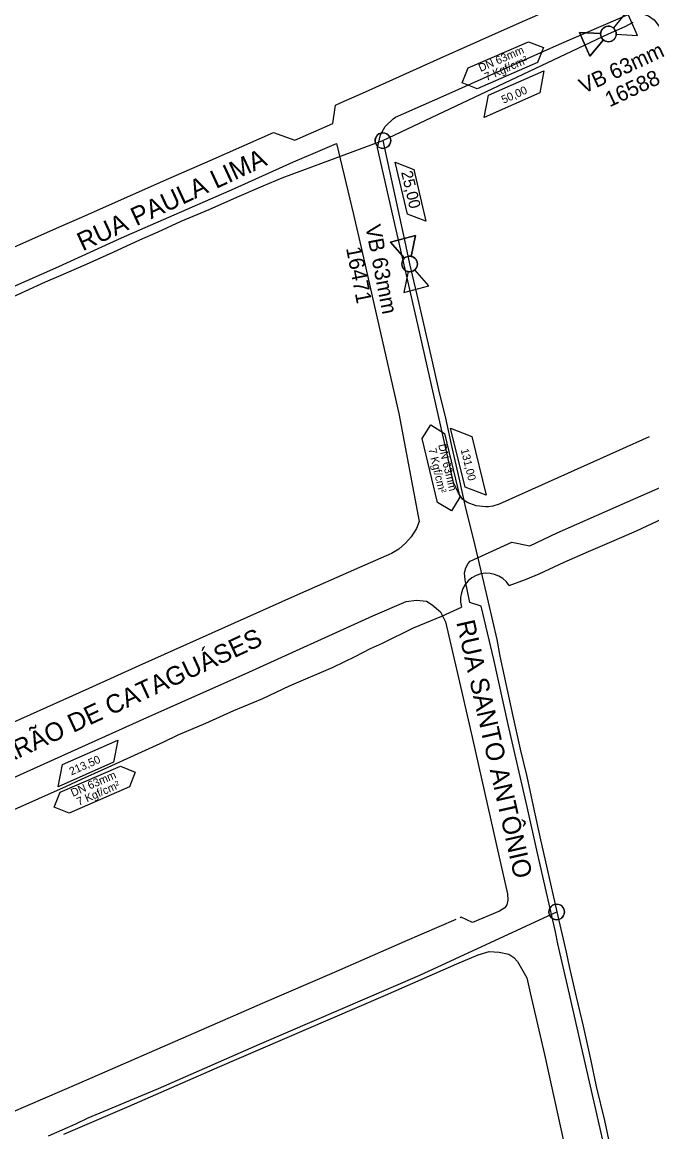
# Model space of a CAD drawing. Extents: x 656692 to 673945, y 7585994 to 7599066.
# Drawn here: x 669344.7 to 669589.7, y 7595459.1 to 7595890.6 of the extents above; entities that cross this region are included whole.
import ezdxf

# ---------------------------------------------------------------- set-up
doc = ezdxf.new("R2010")
doc.units = 0
for name, color, linetype in [('LOGRADOURO', 7, 'Continuous'), ('LOGRADOURO_TEXTO', 7, 'Continuous'), ('SIMBOLO', 7, 'Continuous'), ('TEXTO', 7, 'Continuous'), ('TUBO_PEAD_GN_63', 7, 'Continuous'), ('VALVULA_PEAD_63', 7, 'Continuous')]:
    doc.layers.add(name, color=color, linetype=linetype)

# ---------------------------------------------------------------- blocks, each defined once
blk = doc.blocks.new('VALVULA_PEAD_DN_16')
at = {"layer": 'VALVULA_PEAD_63'}
for points in [[(-0.0374, 0.0187), (-0.1395, 0.0698), (-0.1395, -0.0698), (-0.0374, -0.0187)], [(-0.0374, -0.0187), (-0.1395, -0.0698), (-0.1395, 0.0698), (-0.0374, 0.0187)], [(0.0374, -0.0187), (0.1395, -0.0698), (0.1395, 0.0698), (0.0374, 0.0187)], [(0.0374, -0.0187), (0.1395, -0.0698), (0.1395, 0.0698), (0.0374, 0.0187)]]:
    blk.add_lwpolyline(points, dxfattribs=at)
blk.add_circle((0, 0), 0.0419, dxfattribs=at)
for start, end in [(90, 270), (153.43495, 206.56505), (270, 90), (333.43495, 26.56505)]:
    blk.add_arc((0, 0), 0.0419, start, end, dxfattribs=at)
blk = doc.blocks.new('INTERLIGACAO_9')
at = {"layer": 'SIMBOLO'}
blk.add_circle((0, 0), 4.19, dxfattribs=at)
for start, end in [(0, 180), (180, 0)]:
    blk.add_arc((0, 0), 4.19, start, end, dxfattribs=at)

msp = doc.modelspace()

# ---------------------------------------------------------------- linework, layer by layer
at = {"layer": 'LOGRADOURO'}
for points in [[(669321.54, 7595794.23), (669359.27, 7595810.97), (669367.95, 7595814.75), (669399.74, 7595828.85), (669417.79, 7595836.75), (669442.46, 7595847.64), (669450.75, 7595844.67), (669458.2, 7595847.94), (669465.54, 7595851.19), (669466.64, 7595858.35), (669468.76, 7595859.3), (669477.05, 7595862.95), (669507.28, 7595876.53), (669538.25, 7595890.25), (669575.02, 7595906.45), (669577.47, 7595909.7), (669578.46, 7595912.59), (669578.58, 7595916.4)], [(669553.79, 7595882.06), (669580.42, 7595893.61), (669582.82, 7595894.1), (669585.35, 7595894.02), (669588.34, 7595892.98), (669590.53, 7595891.47), (669592.25, 7595889.23), (669594.49, 7595885.22), (669611.97, 7595846.58), (669622.46, 7595823.54), (669633.74, 7595799.1), (669648.11, 7595768.42), (669649.11, 7595765.62), (669649.81, 7595762.99), (669649.9, 7595759.85), (669649.5, 7595757.16), (669648.42, 7595754.65), (669646.35, 7595751.78), (669644.89, 7595750.78), (669637.86, 7595747.18), (669632.34, 7595749.1), (669607.54, 7595737.68)], [(669588.64, 7595729.3), (669577.06, 7595724.09), (669553.14, 7595713.41), (669530.33, 7595703.1), (669527.84, 7595702.32), (669526.19, 7595702.1), (669525.04, 7595702.06), (669521.31, 7595702.51), (669517.78, 7595703.74), (669515.95, 7595705.11), (669514.4, 7595707.37), (669512.57, 7595711.55), (669508.36, 7595730.02), (669498.59, 7595773), (669489.13, 7595814.3), (669482.92, 7595841.74), (669484.14, 7595846.77), (669485.95, 7595850.02), (669488.98, 7595853), (669489.91, 7595853.6), (669508.44, 7595861.82), (669553.79, 7595882.06)], [(669339.95, 7595787.1), (669358.98, 7595795.58), (669383.37, 7595806.67), (669427.32, 7595825.84), (669450.22, 7595836.2), (669458.87, 7595839.91), (669467.02, 7595843.4), (669473.56, 7595815.84), (669476.8, 7595801.83), (669482.4, 7595777.15), (669491.27, 7595738.35), (669499.13, 7595696.45), (669498.06, 7595693.65), (669496.02, 7595690.42), (669493.83, 7595688.03), (669491.22, 7595685.7), (669488.4, 7595684), (669475.92, 7595678.47), (669450.65, 7595667.31), (669390.14, 7595640.27), (669370.63, 7595631.46), (669317.34, 7595607.55)], [(669573.09, 7595444.9), (669568.9, 7595463.16), (669562.37, 7595492.14), (669557.21, 7595514.33), (669553.14, 7595532.15), (669552.15, 7595536.82), (669545.25, 7595567.44), (669541.15, 7595585.45), (669533.84, 7595617.5), (669528.2, 7595642.69), (669523.3, 7595663.52), (669518.93, 7595664.92), (669517.03, 7595673.72), (669516.85, 7595676.41), (669517.26, 7595678.43), (669518.23, 7595680.04), (669519, 7595680.94), (669535.25, 7595688.41), (669542.22, 7595686.89), (669552.84, 7595691.94), (669583.46, 7595705.45), (669598.26, 7595711.96), (669616.78, 7595720.51), (669639.47, 7595730.71)], [(669325.01, 7595589.52), (669363.93, 7595606.91), (669394.31, 7595620.64), (669431.4, 7595637.21), (669481.17, 7595659.73), (669494.09, 7595665.25), (669498.16, 7595665.86), (669501.97, 7595665.42), (669504.23, 7595664), (669507.42, 7595661.28), (669509.4, 7595657.35), (669513.69, 7595638.94), (669519.77, 7595612.6), (669530.57, 7595564.76), (669533.49, 7595551.63), (669533.59, 7595549.18), (669533.26, 7595547.4), (669532.43, 7595546.14), (669530.42, 7595544.94), (669519.88, 7595540.45), (669515.5, 7595542.51), (669515.11, 7595542.34)], [(669513.4, 7595541.61), (669493.55, 7595533.12), (669466.03, 7595520.98), (669438.14, 7595509.01), (669414.36, 7595498.64), (669366.71, 7595477.88), (669326.95, 7595460.72), (669304.07, 7595450.85)], [(669360.9, 7595458.11), (669386.36, 7595469.04), (669421.67, 7595484.44), (669454.44, 7595498.54), (669486.05, 7595512.23), (669513.84, 7595524.36), (669522.12, 7595527.91), (669526.39, 7595529.22), (669530.32, 7595528.99), (669534.02, 7595528.18), (669535.97, 7595526.88), (669537.46, 7595525.3), (669541.03, 7595518.97), (669542.35, 7595513.18), (669547.97, 7595489.11), (669559.52, 7595436.63)]]:
    msp.add_lwpolyline(points, dxfattribs=at)
at = {"layer": 'SIMBOLO'}
for points in [[(669515.94, 7595866.99), (669518.23, 7595872.81), (669541.66, 7595882.97), (669547.48, 7595880.68), (669545.18, 7595874.86), (669521.76, 7595864.69), (669515.94, 7595866.99)], [(669503.64, 7595733.94), (669508.98, 7595730.68), (669514.95, 7595705.85), (669511.69, 7595700.51), (669506.35, 7595703.78), (669500.38, 7595728.61), (669503.64, 7595733.94)], [(669357.18, 7595585.3), (669359.48, 7595591.12), (669382.9, 7595601.29), (669388.72, 7595598.99), (669386.43, 7595593.17), (669363, 7595583.01), (669357.18, 7595585.3)]]:
    msp.add_lwpolyline(points, dxfattribs=at)
at = {"layer": 'TEXTO'}
for points in [[(669526.18, 7595862.16), (669547.67, 7595871.68), (669546.08, 7595863.07), (669524.46, 7595853.49), (669526.18, 7595862.16)], [(669497.03, 7595833.25), (669501.73, 7595813.2), (669494.57, 7595815.97), (669489.84, 7595836.14), (669497.03, 7595833.25)], [(669519.59, 7595729.5), (669525.26, 7595706.69), (669517.04, 7595709.75), (669511.34, 7595732.7), (669519.59, 7595729.5)], [(669360.38, 7595601.9), (669381.87, 7595611.42), (669380.28, 7595602.8), (669358.65, 7595593.22), (669360.38, 7595601.9)]]:
    msp.add_lwpolyline(points, dxfattribs=at)
at = {"layer": 'TUBO_PEAD_GN_63'}
for points in [[(669485.06, 7595844.51), (669572.79, 7595885.98), (669579.35, 7595888.88), (669582.44, 7595890.56)], [(669337.9, 7595782.4), (669353.72, 7595789.54), (669359.02, 7595791.84), (669369.77, 7595796.5), (669380.06, 7595801.19), (669390.54, 7595805.97), (669397.68, 7595809.03), (669406.62, 7595813.24), (669417.46, 7595817.73), (669428.23, 7595822.52), (669438.45, 7595826.88), (669445.85, 7595830.08), (669485.06, 7595844.51)], [(669485.06, 7595844.51), (669493.45, 7595805.75), (669495.45, 7595796.53), (669498.62, 7595782.79), (669504.03, 7595759.12), (669506.66, 7595747.65), (669509.35, 7595736.59), (669511.87, 7595725.18), (669514.58, 7595713.35), (669517.22, 7595701.58), (669520.15, 7595689.77), (669524.35, 7595672.34), (669529.42, 7595650.54), (669530.6, 7595644), (669535.6, 7595620.72), (669538.49, 7595607.81), (669541.01, 7595597.26), (669543.49, 7595585.71), (669546.04, 7595573.84), (669548.93, 7595561.24), (669552.65, 7595544.57), (669556.39, 7595528.95), (669557.56, 7595523.3), (669560.26, 7595511.6), (669562.9, 7595500.12), (669565.79, 7595487.32), (669568.02, 7595476.76), (669571.25, 7595463.49), (669573.34, 7595453.61)], [(669534.22, 7595671.46), (669540.46, 7595673.9), (669545.8, 7595675.99), (669555.57, 7595680.54), (669564.97, 7595684.69), (669573.21, 7595688.27), (669583.77, 7595692.82), (669593.9, 7595697.51), (669601.58, 7595701.04), (669611.21, 7595705.07), (669632.67, 7595714.76), (669640.62, 7595717.97), (669644.11, 7595719.62), (669649.04, 7595722.14), (669654.7, 7595724.55), (669659.88, 7595726.68), (669667.27, 7595729.71)], [(669340.44, 7595583.88), (669351.19, 7595588.66), (669361.92, 7595593.54), (669367.79, 7595596.2), (669378.21, 7595600.89), (669388.44, 7595605.5), (669399.78, 7595610.77), (669405.46, 7595613.42), (669416.1, 7595618.04), (669427.09, 7595622.87), (669438.29, 7595627.63), (669448.65, 7595632.52), (669465.71, 7595639.79), (669474.26, 7595643.95), (669480.25, 7595647.02), (669484.94, 7595649.04), (669496.96, 7595654.99), (669507.94, 7595659.63), (669515.65, 7595663.13)], [(669354.95, 7595457.47), (669365.61, 7595462.23), (669370.33, 7595464.49), (669397.79, 7595475.97), (669436.98, 7595493.1), (669499.44, 7595519.97), (669552.65, 7595544.57)]]:
    msp.add_lwpolyline(points, dxfattribs=at)
msp.add_arc((669525.5, 7595666.03), 10.27, 31.9554, 196.3817, dxfattribs=at)

# ---------------------------------------------------------------- block references
at = {"layer": 'SIMBOLO', "xscale": 0.7229249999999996, "yscale": 0.7229249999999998, "rotation": 166.312122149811}
for p in [(669485.06, 7595844.51), (669552.65, 7595544.57)]:
    msp.add_blockref('INTERLIGACAO_9', p, dxfattribs=at)
at = {"layer": 'VALVULA_PEAD_63'}
for p, xscale, yscale, rotation in [((669572.79, 7595885.98), 72.29249999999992, 72.29249999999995, 23.827974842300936), ((669495.45, 7595796.53), 72.29249999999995, 72.29249999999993, -75.20019756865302)]:
    msp.add_blockref('VALVULA_PEAD_DN_16', p, dxfattribs=dict(at, xscale=xscale, yscale=yscale, rotation=rotation))

# ---------------------------------------------------------------- texts
for s, rotation, p in [('VB 63mm', 25.048, (669563.14, 7595862.61)), ('16588', 25.048, (669573.23, 7595857.41)), ('VB 63mm', 281.048, (669478.18, 7595811.22)), ('16471', 281.048, (669470.69, 7595802.69))]:
    msp.add_text(s, height=6, rotation=rotation).set_placement(p)
at = {"layer": 'LOGRADOURO_TEXTO'}
for s, rotation, p in [('RUA PAULA LIMA', 25, (669368.22, 7595801.44)), ('RUA SANTO ANTÔNIO', 282.7896, (669513.56, 7595657.25)), ('RUA BARÃO DE CATAGUÁSES', 24.9182, (669310.67, 7595589.1))]:
    msp.add_text(s, height=7.2, rotation=rotation, dxfattribs=at).set_placement(p)
at = {"layer": 'TEXTO'}
for s, height, rotation, p in [('DN 63mm', 3.113, 23.4657, (669523.07, 7595871.18)), ('7 Kgf/cm²', 3.113, 23.4657, (669525.38, 7595867.68)), ('50,00', 3.113, 23.8883, (669531.99, 7595858.81)), ('25,00', 4.447, 283.1976, (669492.1, 7595832.24)), ('7 Kgf/cm²', 3.113, 283.532, (669502.7, 7595724.53)), ('DN 63mm', 3.113, 283.532, (669506.54, 7595726.2)), ('131,00', 3.113, 283.9546, (669515.28, 7595724.36)), ('213,50', 3.113, 23.8883, (669363.84, 7595597.63)), ('DN 63mm', 3.113, 23.4657, (669364.42, 7595589.29)), ('7 Kgf/cm²', 3.113, 23.4657, (669366.73, 7595585.79))]:
    msp.add_text(s, height=height, rotation=rotation, dxfattribs=at).set_placement(p)

doc.saveas('drawing.dxf')
